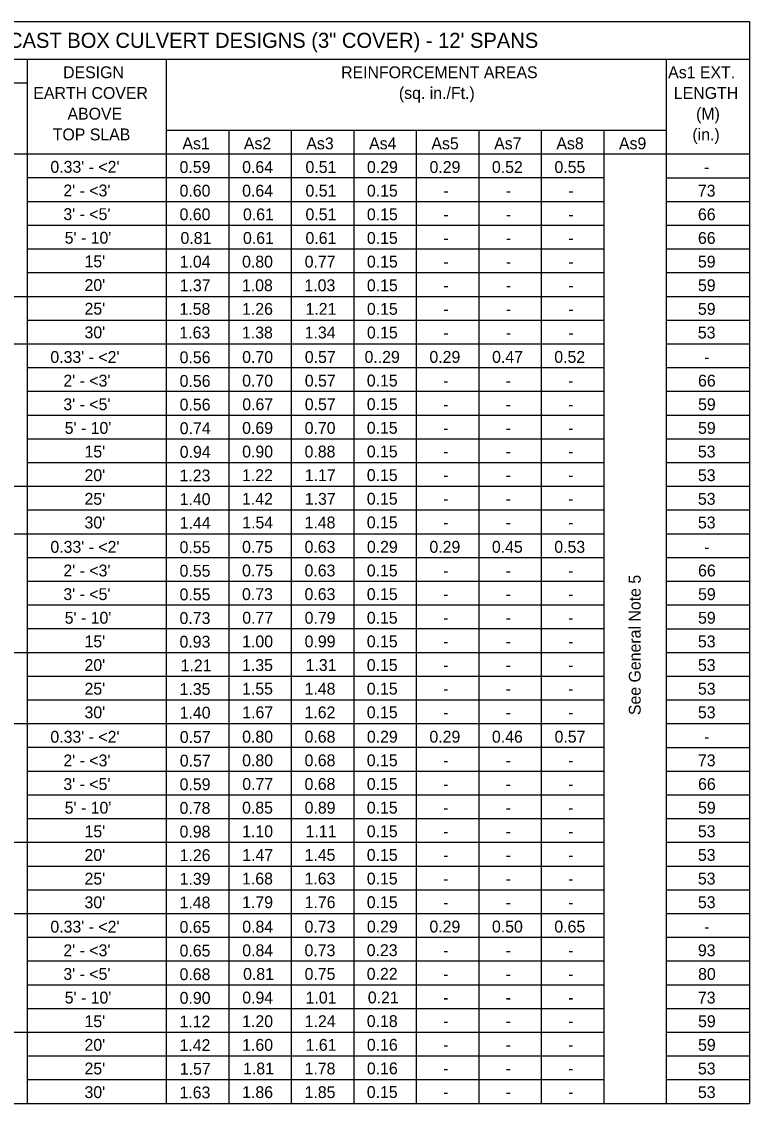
# Model space of a CAD drawing. Extents: x 10340.6 to 10376, y 76398.7 to 76415.8.
# Drawn here: x 10344.36 to 10350.55, y 76405.12 to 76414.31 of the extents above; entities that cross this region are included whole.
import ezdxf

# ---------------------------------------------------------------- set-up
doc = ezdxf.new("R2010")
doc.units = 0
doc.layers.add('AdhocPoint_dp', color=7, linetype='Continuous')
doc.layers.add('PlotBorder_dp', color=7, linetype='Continuous')

msp = doc.modelspace()

# ---------------------------------------------------------------- linework, layer by layer
at = {"layer": 'PlotBorder_dp'}
for p, q in [((10341.0317, 76414.3084), (10350.5475, 76414.3084)), ((10350.5475, 76414.3084), (10350.5475, 76405.1209)), ((10341.0317, 76413.9906), (10350.5475, 76413.9906)), ((10344.409, 76413.9906), (10344.409, 76405.1209)), ((10345.5911, 76413.9906), (10345.5911, 76405.1209)), ((10349.8405, 76413.9906), (10349.8405, 76405.1209)), ((10342.1299, 76413.789), (10344.409, 76413.789)), ((10345.5911, 76413.3866), (10349.8405, 76413.3866)), ((10346.1223, 76413.3866), (10346.1223, 76405.1209)), ((10346.6534, 76413.3866), (10346.6534, 76405.1209)), ((10347.1846, 76413.3866), (10347.1846, 76405.1209)), ((10347.7158, 76413.3866), (10347.7158, 76405.1209)), ((10348.247, 76413.3866), (10348.247, 76405.1209)), ((10348.247, 76413.3866), (10348.247, 76405.1209)), ((10348.7781, 76413.3866), (10348.7781, 76405.1209)), ((10349.3093, 76413.3866), (10349.3093, 76405.1209)), ((10341.0317, 76413.185), (10350.5475, 76413.185)), ((10344.409, 76412.9833), (10349.3093, 76412.9833)), ((10349.8405, 76412.983), (10350.5475, 76412.983)), ((10344.409, 76412.7817), (10349.3093, 76412.7817)), ((10349.8405, 76412.7814), (10350.5475, 76412.7814)), ((10344.409, 76412.5801), (10349.3093, 76412.5801)), ((10349.8405, 76412.5798), (10350.5475, 76412.5798)), ((10344.409, 76412.3785), (10349.3093, 76412.3785)), ((10349.8405, 76412.3782), (10350.5475, 76412.3782)), ((10344.409, 76412.1769), (10349.3093, 76412.1769)), ((10349.8405, 76412.1766), (10350.5475, 76412.1766)), ((10342.1299, 76411.9753), (10349.3093, 76411.9753)), ((10349.8405, 76411.975), (10350.5475, 76411.975)), ((10344.409, 76411.7737), (10349.3093, 76411.7737)), ((10349.8405, 76411.7734), (10350.5475, 76411.7734)), ((10341.0317, 76411.5721), (10349.3093, 76411.5721)), ((10344.4191, 76411.5718), (10345.5739, 76411.5718)), ((10349.8405, 76411.5718), (10350.5475, 76411.5718)), ((10344.409, 76411.3705), (10349.3093, 76411.3705)), ((10349.8405, 76411.3702), (10350.5475, 76411.3702)), ((10344.409, 76411.1689), (10349.3093, 76411.1689)), ((10349.8405, 76411.1686), (10350.5475, 76411.1686)), ((10344.409, 76410.9673), (10349.3093, 76410.9673)), ((10349.8405, 76410.967), (10350.5475, 76410.967)), ((10344.409, 76410.7657), (10349.3093, 76410.7657)), ((10349.8405, 76410.7654), (10350.5475, 76410.7654)), ((10344.409, 76410.5641), (10349.3093, 76410.5641)), ((10349.8405, 76410.5638), (10350.5475, 76410.5638)), ((10342.1299, 76410.3625), (10349.3093, 76410.3625)), ((10349.8405, 76410.3622), (10350.5475, 76410.3622)), ((10344.409, 76410.1609), (10349.3093, 76410.1609)), ((10344.409, 76410.1606), (10345.5739, 76410.1606)), ((10349.8405, 76410.1606), (10350.5475, 76410.1606)), ((10341.0317, 76409.9593), (10349.3093, 76409.9593)), ((10349.8405, 76409.959), (10350.5475, 76409.959)), ((10344.409, 76409.7577), (10349.3093, 76409.7577)), ((10349.8405, 76409.7574), (10350.5475, 76409.7574)), ((10344.409, 76409.5561), (10349.3093, 76409.5561)), ((10349.8405, 76409.5558), (10350.5475, 76409.5558)), ((10344.409, 76409.3545), (10349.3093, 76409.3545)), ((10349.8405, 76409.3542), (10350.5475, 76409.3542)), ((10344.409, 76409.1529), (10349.3093, 76409.1529)), ((10349.8405, 76409.1526), (10350.5475, 76409.1526)), ((10342.1299, 76408.9513), (10344.409, 76408.9513)), ((10344.409, 76408.9513), (10349.3093, 76408.9513)), ((10349.8405, 76408.951), (10350.5475, 76408.951)), ((10344.409, 76408.7497), (10349.3093, 76408.7497)), ((10349.8405, 76408.7494), (10350.5475, 76408.7494)), ((10344.409, 76408.5481), (10349.3093, 76408.5481)), ((10349.8405, 76408.5478), (10350.5475, 76408.5478)), ((10341.0317, 76408.3465), (10349.3093, 76408.3465)), ((10344.4191, 76408.3462), (10345.5739, 76408.3462)), ((10349.8405, 76408.3462), (10350.5475, 76408.3462)), ((10344.409, 76408.1449), (10349.3093, 76408.1449)), ((10349.8405, 76408.1446), (10350.5475, 76408.1446)), ((10344.409, 76407.9433), (10349.3093, 76407.9433)), ((10349.8405, 76407.943), (10350.5475, 76407.943)), ((10344.409, 76407.7417), (10349.3093, 76407.7417)), ((10349.8405, 76407.7414), (10350.5475, 76407.7414)), ((10344.409, 76407.5401), (10349.3093, 76407.5401)), ((10349.8405, 76407.5398), (10350.5475, 76407.5398)), ((10342.1299, 76407.3385), (10344.409, 76407.3385)), ((10344.409, 76407.3385), (10349.3093, 76407.3385)), ((10349.8405, 76407.3382), (10350.5475, 76407.3382)), ((10344.409, 76407.1369), (10349.3093, 76407.1369)), ((10349.8405, 76407.1366), (10350.5475, 76407.1366)), ((10344.409, 76406.9353), (10349.3093, 76406.9353)), ((10349.8405, 76406.935), (10350.5475, 76406.935)), ((10341.0317, 76406.7337), (10349.3093, 76406.7337)), ((10344.4191, 76406.7334), (10345.5739, 76406.7334)), ((10349.8405, 76406.7334), (10350.5475, 76406.7334)), ((10344.409, 76406.5321), (10349.3093, 76406.5321)), ((10349.8405, 76406.5318), (10350.5475, 76406.5318)), ((10344.409, 76406.3305), (10349.3093, 76406.3305)), ((10349.8405, 76406.3302), (10350.5475, 76406.3302)), ((10344.409, 76406.1289), (10349.3093, 76406.1289)), ((10349.8405, 76406.1286), (10350.5475, 76406.1286)), ((10344.409, 76405.9273), (10349.3093, 76405.9273)), ((10349.8405, 76405.927), (10350.5475, 76405.927)), ((10342.1299, 76405.7257), (10344.409, 76405.7257)), ((10344.409, 76405.7257), (10349.3093, 76405.7257)), ((10349.8405, 76405.7254), (10350.5475, 76405.7254)), ((10344.409, 76405.5241), (10349.3093, 76405.5241)), ((10349.8405, 76405.5238), (10350.5475, 76405.5238)), ((10344.409, 76405.3225), (10349.3093, 76405.3225)), ((10349.8405, 76405.3222), (10350.5475, 76405.3222)), ((10341.0317, 76405.1209), (10350.5475, 76405.1209))]:
    msp.add_line(p, q, dxfattribs=at)

# ---------------------------------------------------------------- texts
at = {"layer": 'AdhocPoint_dp'}
for s, height, p in [('TABLE 16 - STANDARD PRECAST BOX CULVERT DESIGNS (3" COVER) - 12\' SPANS', 0.128, (10341.9731, 76414.0855)), ('As1', 0.1008, (10345.729, 76413.2238)), ('As2', 0.1008, (10346.2511, 76413.2238)), ('As3', 0.1008, (10346.7822, 76413.2238)), ('As4', 0.1008, (10347.3155, 76413.2238)), ('As5', 0.1008, (10347.8451, 76413.2238)), ('As7', 0.1008, (10348.3785, 76413.2238)), ('As8', 0.1008, (10348.9073, 76413.2238)), ('As9', 0.1008, (10349.4392, 76413.2238))]:
    msp.add_text(s, height=height, dxfattribs=at).set_placement(p)
msp.add_text('See General Note 5', height=0.1008, rotation=90, dxfattribs=at).set_placement((10349.6237, 76408.4185))
at = {"layer": 'PlotBorder_dp'}
for s, p in [('DESIGN', (10344.7146, 76413.828)), ('REINFORCEMENT AREAS', (10347.0775, 76413.828)), ('EARTH COVER', (10344.4619, 76413.652)), ('(sq. in./Ft.)', (10347.5686, 76413.652)), ('ABOVE', (10344.7522, 76413.476)), ('TOP SLAB', (10344.6269, 76413.3)), ("0.33' - <2'", (10344.6067, 76413.0247)), ('0.59', (10345.7045, 76413.023)), ('0.64', (10346.2366, 76413.023)), ('0.51', (10346.7749, 76413.023)), ('0.29', (10347.2974, 76413.023)), ('0.29', (10347.8291, 76413.023)), ('0.52', (10348.3594, 76413.023)), ('0.55', (10348.8908, 76413.023)), ("2' - <3'", (10344.7171, 76412.8239)), ('0.60', (10345.7047, 76412.8222)), ('0.64', (10346.2366, 76412.8222)), ('0.51', (10346.7749, 76412.8222)), ('0.15', (10347.2968, 76412.8222)), ('-', (10347.9465, 76412.8222)), ('-', (10348.4779, 76412.8222)), ('-', (10349.0088, 76412.8222)), ("3' - <5'", (10344.7171, 76412.6231)), ('0.60', (10345.7047, 76412.6214)), ('0.61', (10346.2437, 76412.6214)), ('0.51', (10346.7749, 76412.6214)), ('0.15', (10347.2968, 76412.6214)), ('-', (10347.9465, 76412.6214)), ('-', (10348.4779, 76412.6214)), ('-', (10349.0088, 76412.6214)), ("5' - 10'", (10344.7285, 76412.4223)), ('0.81', (10345.7125, 76412.4206)), ('0.61', (10346.2437, 76412.4206)), ('0.61', (10346.7749, 76412.4206)), ('0.15', (10347.2968, 76412.4206)), ('-', (10347.9465, 76412.4206)), ('-', (10348.4779, 76412.4206)), ('-', (10349.0088, 76412.4206)), ("15'", (10344.8968, 76412.2215)), ('1.04', (10345.7054, 76412.2198)), ('0.80', (10346.2359, 76412.2198)), ('0.77', (10346.7681, 76412.2198)), ('0.15', (10347.2968, 76412.2198)), ('-', (10347.9465, 76412.2198)), ('-', (10348.4779, 76412.2198)), ('-', (10349.0088, 76412.2198)), ("20'", (10344.8968, 76412.0207)), ('1.37', (10345.7057, 76412.019)), ('1.08', (10346.2349, 76412.019)), ('1.03', (10346.7658, 76412.019)), ('0.15', (10347.2968, 76412.019)), ('-', (10347.9465, 76412.019)), ('-', (10348.4779, 76412.019)), ('-', (10349.0088, 76412.019)), ("25'", (10344.8968, 76411.8199)), ('1.58', (10345.7037, 76411.8182)), ('1.26', (10346.2357, 76411.8182)), ('1.21', (10346.7749, 76411.8182)), ('0.15', (10347.2968, 76411.8182)), ('-', (10347.9465, 76411.8182)), ('-', (10348.4779, 76411.8182)), ('-', (10349.0088, 76411.8182)), ("30'", (10344.8968, 76411.6191)), ('1.63', (10345.7034, 76411.6174)), ('1.38', (10346.2349, 76411.6174)), ('1.34', (10346.7678, 76411.6174)), ('0.15', (10347.2968, 76411.6174)), ('-', (10347.9465, 76411.6174)), ('-', (10348.4779, 76411.6174)), ('-', (10349.0088, 76411.6174)), ("0.33' - <2'", (10344.6067, 76411.4097)), ('0.56', (10345.7053, 76411.4072)), ('0.70', (10346.2367, 76411.4097)), ('0.57', (10346.769, 76411.4097)), ('0..29', (10347.2767, 76411.4105)), ('0.29', (10347.8283, 76411.4105)), ('0.47', (10348.3609, 76411.4105)), ('0.52', (10348.8895, 76411.4105)), ('-', (10350.1636, 76411.4097)), ("2' - <3'", (10344.7171, 76411.2089)), ('0.56', (10345.7053, 76411.2064)), ('0.70', (10346.2367, 76411.2089)), ('0.57', (10346.769, 76411.2089)), ('0.15', (10347.2959, 76411.2097)), ('66', (10350.1114, 76411.2089)), ('-', (10347.9457, 76411.2097)), ('-', (10348.477, 76411.2097)), ('-', (10349.008, 76411.2097)), ("3' - <5'", (10344.7171, 76411.0081)), ('0.56', (10345.7053, 76411.0056)), ('0.67', (10346.2377, 76411.0081)), ('0.57', (10346.769, 76411.0081)), ('0.15', (10347.2959, 76411.0089)), ('59', (10350.1114, 76411.0081)), ('-', (10347.9457, 76411.0089)), ('-', (10348.477, 76411.0089)), ('-', (10349.008, 76411.0089)), ("5' - 10'", (10344.7285, 76410.8073)), ('0.74', (10345.7063, 76410.8048)), ('0.69', (10346.2365, 76410.8073)), ('0.70', (10346.7679, 76410.8073)), ('0.15', (10347.2959, 76410.8081)), ('59', (10350.1114, 76410.8073)), ('-', (10347.9457, 76410.8081)), ('-', (10348.477, 76410.8081)), ('-', (10349.008, 76410.8081)), ("15'", (10344.8968, 76410.6065)), ('0.94', (10345.7063, 76410.604)), ('0.90', (10346.2367, 76410.6065)), ('0.88', (10346.767, 76410.6065)), ('0.15', (10347.2959, 76410.6073)), ('53', (10350.1102, 76410.6065)), ('-', (10347.9457, 76410.6073)), ('-', (10348.477, 76410.6073)), ('-', (10349.008, 76410.6073)), ("20'", (10344.8968, 76410.4057)), ('1.23', (10345.7042, 76410.4032)), ('1.22', (10346.2355, 76410.4057)), ('1.17', (10346.769, 76410.4057)), ('0.15', (10347.2959, 76410.4065)), ('-', (10347.9457, 76410.4065)), ('-', (10348.477, 76410.4065)), ('-', (10349.008, 76410.4065)), ('53', (10350.1102, 76410.4057)), ("25'", (10344.8968, 76410.2049)), ('1.40', (10345.7056, 76410.2024)), ('1.42', (10346.2355, 76410.2049)), ('1.37', (10346.769, 76410.2049)), ('0.15', (10347.2959, 76410.2057)), ('-', (10347.9457, 76410.2057)), ('-', (10348.477, 76410.2057)), ('-', (10349.008, 76410.2057)), ('53', (10350.1102, 76410.2049)), ("30'", (10344.8968, 76410.0041)), ('1.44', (10345.7063, 76410.0016)), ('1.54', (10346.2375, 76410.0041)), ('1.48', (10346.767, 76410.0041)), ('0.15', (10347.2959, 76410.0049)), ('53', (10350.1102, 76410.0041)), ('-', (10347.9457, 76410.0049)), ('-', (10348.477, 76410.0049)), ('-', (10349.008, 76410.0049)), ("0.33' - <2'", (10344.6067, 76409.7972)), ('0.55', (10345.7047, 76409.7947)), ('0.75', (10346.2359, 76409.7972)), ('0.63', (10346.7666, 76409.7972)), ('0.29', (10347.2966, 76409.7972)), ('0.29', (10347.8283, 76409.7972)), ('0.45', (10348.359, 76409.7972)), ('0.53', (10348.8894, 76409.7972)), ('-', (10350.1636, 76409.7972)), ("2' - <3'", (10344.7171, 76409.5964)), ('0.55', (10345.7047, 76409.5939)), ('0.75', (10346.2359, 76409.5964)), ('0.63', (10346.7666, 76409.5964)), ('0.15', (10347.2959, 76409.5964)), ('66', (10350.1114, 76409.5964)), ('-', (10347.9457, 76409.5964)), ('-', (10348.477, 76409.5964)), ('-', (10349.008, 76409.5964)), ("3' - <5'", (10344.7171, 76409.3956)), ('0.55', (10345.7047, 76409.3931)), ('0.73', (10346.2354, 76409.3956)), ('0.63', (10346.7666, 76409.3956)), ('0.15', (10347.2959, 76409.3956)), ('-', (10347.9457, 76409.3956)), ('-', (10348.477, 76409.3956)), ('-', (10349.008, 76409.3956)), ('59', (10350.1114, 76409.3956)), ("5' - 10'", (10344.7285, 76409.1948)), ('0.73', (10345.7042, 76409.1923)), ('0.77', (10346.2377, 76409.1948)), ('0.79', (10346.7677, 76409.1948)), ('0.15', (10347.2959, 76409.1948)), ('-', (10347.9457, 76409.1948)), ('-', (10348.477, 76409.1948)), ('-', (10349.008, 76409.1948)), ('59', (10350.1114, 76409.1948)), ("15'", (10344.8968, 76408.994)), ('0.93', (10345.7042, 76408.9915)), ('1.00', (10346.2367, 76408.994)), ('0.99', (10346.7677, 76408.994)), ('0.15', (10347.2959, 76408.994)), ('53', (10350.1102, 76408.994)), ('-', (10347.9457, 76408.994)), ('-', (10348.477, 76408.994)), ('-', (10349.008, 76408.994)), ("20'", (10344.8968, 76408.7932)), ('1.21', (10345.7134, 76408.7907)), ('1.35', (10346.2359, 76408.7932)), ('1.31', (10346.7758, 76408.7932)), ('0.15', (10347.2959, 76408.7932)), ('53', (10350.1102, 76408.7932)), ('-', (10347.9457, 76408.7932)), ('-', (10348.477, 76408.7932)), ('-', (10349.008, 76408.7932)), ("25'", (10344.8968, 76408.5924)), ('1.35', (10345.7047, 76408.5899)), ('1.55', (10346.2359, 76408.5924)), ('1.48', (10346.767, 76408.5924)), ('0.15', (10347.2959, 76408.5924)), ('53', (10350.1102, 76408.5924)), ('-', (10347.9457, 76408.5924)), ('-', (10348.477, 76408.5924)), ('-', (10349.008, 76408.5924)), ("30'", (10344.8968, 76408.3916)), ('1.40', (10345.7056, 76408.3891)), ('1.67', (10346.2377, 76408.3916)), ('1.62', (10346.7667, 76408.3916)), ('0.15', (10347.2959, 76408.3916)), ('-', (10347.9457, 76408.3916)), ('-', (10348.477, 76408.3916)), ('-', (10349.008, 76408.3916)), ('53', (10350.1102, 76408.3916)), ("0.33' - <2'", (10344.6067, 76408.1839)), ('0.57', (10345.7066, 76408.1822)), ('0.80', (10346.2367, 76408.1847)), ('0.68', (10346.767, 76408.1847)), ('0.29', (10347.2966, 76408.1847)), ('0.29', (10347.8283, 76408.1847)), ('0.46', (10348.3596, 76408.1847)), ('0.57', (10348.8918, 76408.1847)), ('-', (10350.1636, 76408.1847)), ("2' - <3'", (10344.7171, 76407.9831)), ('0.57', (10345.7066, 76407.9814)), ('0.80', (10346.2367, 76407.9839)), ('0.68', (10346.767, 76407.9839)), ('0.15', (10347.2959, 76407.9839)), ('73', (10350.1102, 76407.9839)), ('-', (10347.9457, 76407.9839)), ('-', (10348.477, 76407.9839)), ('-', (10349.008, 76407.9839)), ("3' - <5'", (10344.7171, 76407.7823)), ('0.59', (10345.7053, 76407.7806)), ('0.77', (10346.2377, 76407.7831)), ('0.68', (10346.767, 76407.7831)), ('0.15', (10347.2959, 76407.7831)), ('66', (10350.1114, 76407.7831)), ('-', (10347.9457, 76407.7831)), ('-', (10348.477, 76407.7831)), ('-', (10349.008, 76407.7831)), ("5' - 10'", (10344.7285, 76407.5815)), ('0.78', (10345.7046, 76407.5798)), ('0.85', (10346.2359, 76407.5823)), ('0.89', (10346.7677, 76407.5823)), ('0.15', (10347.2959, 76407.5823)), ('59', (10350.1114, 76407.5823)), ('-', (10347.9457, 76407.5823)), ('-', (10348.477, 76407.5823)), ('-', (10349.008, 76407.5823)), ("15'", (10344.8968, 76407.3807)), ('0.98', (10345.7046, 76407.379)), ('1.10', (10346.2367, 76407.3815)), ('1.11', (10346.7758, 76407.3815)), ('0.15', (10347.2959, 76407.3815)), ('-', (10347.9457, 76407.3815)), ('-', (10348.477, 76407.3815)), ('-', (10349.008, 76407.3815)), ('53', (10350.1102, 76407.3815)), ("20'", (10344.8968, 76407.1799)), ('1.26', (10345.7053, 76407.1782)), ('1.47', (10346.2377, 76407.1807)), ('1.45', (10346.7671, 76407.1807)), ('0.15', (10347.2959, 76407.1807)), ('-', (10347.9457, 76407.1807)), ('-', (10348.477, 76407.1807)), ('-', (10349.008, 76407.1807)), ('53', (10350.1102, 76407.1807)), ("25'", (10344.8968, 76406.9791)), ('1.39', (10345.7053, 76406.9774)), ('1.68', (10346.2358, 76406.9799)), ('1.63', (10346.7666, 76406.9799)), ('0.15', (10347.2959, 76406.9799)), ('53', (10350.1102, 76406.9799)), ('-', (10347.9457, 76406.9799)), ('-', (10348.477, 76406.9799)), ('-', (10349.008, 76406.9799)), ("30'", (10344.8968, 76406.7783)), ('1.48', (10345.7046, 76406.7766)), ('1.79', (10346.2365, 76406.7791)), ('1.76', (10346.7677, 76406.7791)), ('0.15', (10347.2959, 76406.7791)), ('53', (10350.1102, 76406.7791)), ('-', (10347.9457, 76406.7791)), ('-', (10348.477, 76406.7791)), ('-', (10349.008, 76406.7791)), ("0.33' - <2'", (10344.6067, 76406.5714)), ('0.65', (10345.7047, 76406.5689)), ('0.84', (10346.2375, 76406.5714)), ('0.73', (10346.7666, 76406.5714)), ('0.29', (10347.2966, 76406.5722)), ('0.29', (10347.8283, 76406.5722)), ('0.50', (10348.3598, 76406.5722)), ('0.65', (10348.8899, 76406.5722)), ('-', (10350.1636, 76406.5714)), ("2' - <3'", (10344.7171, 76406.3706)), ('0.65', (10345.7047, 76406.3681)), ('0.84', (10346.2375, 76406.3706)), ('0.73', (10346.7666, 76406.3706)), ('0.23', (10347.2954, 76406.3714)), ('-', (10347.9457, 76406.3714)), ('-', (10348.477, 76406.3714)), ('-', (10349.008, 76406.3714)), ('93', (10350.1102, 76406.3706)), ("3' - <5'", (10344.7171, 76406.1698)), ('0.68', (10345.7046, 76406.1673)), ('0.81', (10346.2445, 76406.1698)), ('0.75', (10346.7671, 76406.1698)), ('0.22', (10347.2955, 76406.1706)), ('-', (10347.9457, 76406.1706)), ('-', (10348.477, 76406.1706)), ('-', (10349.008, 76406.1706)), ('80', (10350.1116, 76406.1698)), ("5' - 10'", (10344.7285, 76405.969)), ('0.90', (10345.7056, 76405.9665)), ('0.94', (10346.2375, 76405.969)), ('1.01', (10346.7758, 76405.969)), ('0.21', (10347.3046, 76405.9698)), ('73', (10350.1102, 76405.969)), ('-', (10347.9457, 76405.9698)), ('-', (10348.477, 76405.9698)), ('-', (10349.008, 76405.9698)), ("15'", (10344.8968, 76405.7682)), ('1.12', (10345.7043, 76405.7657)), ('1.20', (10346.2367, 76405.7682)), ('1.24', (10346.7687, 76405.7682)), ('0.18', (10347.2958, 76405.769)), ('59', (10350.1114, 76405.7682)), ('-', (10347.9457, 76405.769)), ('-', (10348.477, 76405.769)), ('-', (10349.008, 76405.769)), ("20'", (10344.8968, 76405.5674)), ('1.42', (10345.7043, 76405.5649)), ('1.60', (10346.2367, 76405.5674)), ('1.61', (10346.7758, 76405.5674)), ('0.16', (10347.2966, 76405.5682)), ('59', (10350.1114, 76405.5674)), ('-', (10347.9457, 76405.5682)), ('-', (10348.477, 76405.5682)), ('-', (10349.008, 76405.5682)), ("25'", (10344.8968, 76405.3666)), ('1.81', (10346.2445, 76405.3666)), ('1.78', (10346.767, 76405.3666)), ('0.16', (10347.2966, 76405.3674)), ('53', (10350.1102, 76405.3666)), ('1.57', (10345.7066, 76405.3641)), ('-', (10347.9457, 76405.3674)), ('-', (10348.477, 76405.3674)), ('-', (10349.008, 76405.3674)), ("30'", (10344.8968, 76405.1658)), ('1.63', (10345.7042, 76405.1633)), ('1.86', (10346.2365, 76405.1658)), ('1.85', (10346.7671, 76405.1658)), ('0.15', (10347.2959, 76405.1666)), ('-', (10347.9457, 76405.1666)), ('-', (10348.477, 76405.1666)), ('-', (10349.008, 76405.1666)), ('53', (10350.1102, 76405.1658))]:
    msp.add_text(s, height=0.1008, dxfattribs=at).set_placement(p)
for s, p in [('As1 EXT.', (10349.8572, 76413.828)), ('LENGTH', (10349.9056, 76413.652)), ('(M)', (10350.0946, 76413.476)), ('(in.)', (10350.0632, 76413.3)), ('-', (10350.1628, 76413.023)), ('73', (10350.1094, 76412.8222)), ('66', (10350.1105, 76412.6214)), ('66', (10350.1105, 76412.4206)), ('59', (10350.1105, 76412.2198)), ('59', (10350.1105, 76412.019)), ('59', (10350.1105, 76411.8182)), ('53', (10350.1094, 76411.6174))]:
    msp.add_text(s, height=0.1008, rotation=360, dxfattribs=at).set_placement(p)

doc.saveas('drawing.dxf')
